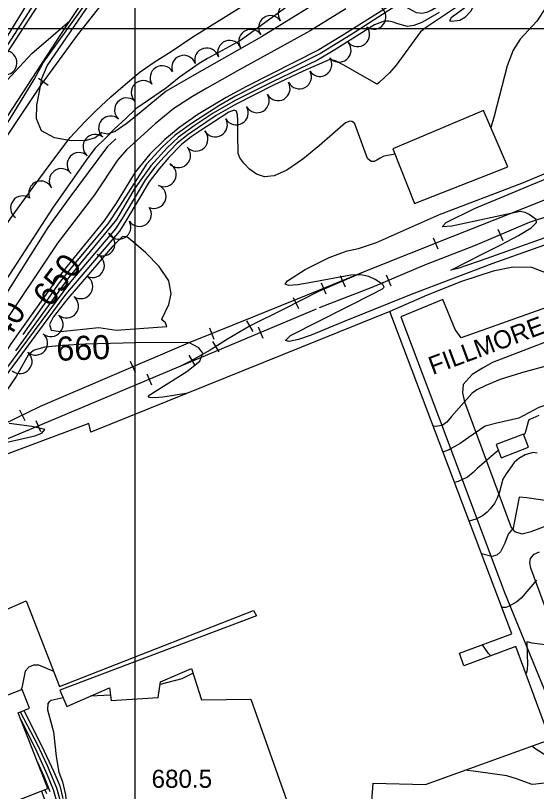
# Model space of a CAD drawing. Extents: x 79600 to 91800, y 75600 to 84400.
# Drawn here: x 83901 to 84333, y 81367 to 82011 of the extents above; entities that cross this region are included whole.
import ezdxf

# ---------------------------------------------------------------- set-up
doc = ezdxf.new("R2010")
doc.units = 0
for name, color, linetype in [('084-085$0$BLDG', 7, 'Continuous'), ('084-085$0$GRID', 7, 'Continuous'), ('084-085$0$INDEX', 7, 'Continuous'), ('084-085$0$INDXLBL', 7, 'Continuous'), ('084-085$0$INTER', 7, 'Continuous'), ('084-085$0$ROAD', 7, 'Continuous'), ('084-085$0$ROAD-NAME', 7, 'Continuous'), ('084-085$0$RR', 7, 'Continuous'), ('084-085$0$SPOTS', 7, 'Continuous'), ('084-085$0$TREES', 7, 'Continuous'), ('084-085$0$WALL', 7, 'Continuous')]:
    doc.layers.add(name, color=color, linetype=linetype)

# ---------------------------------------------------------------- blocks, each defined once
blk = doc.blocks.new('084-085$0$RRTICK100')
blk.add_line((0, -5), (0, 5))

msp = doc.modelspace()

# ---------------------------------------------------------------- linework, layer by layer
at = {"layer": '084-085$0$BLDG'}
for points in [[(84288.98, 81932.31), (84213.95, 81900.38), (84231.85, 81855.01), (84309.2, 81885.58)], [(84322.12, 81663.87), (84299.39, 81655.24), (84303.56, 81644.27), (84326.29, 81652.9)], [(83903.22, 81432.79), (83912.76, 81436.51), (83906.65, 81452.17), (83842.05, 81426.99), (83872.69, 81348.38), (83927.75, 81369.83)]]:
    msp.add_lwpolyline(points, close=True, dxfattribs=at)
for points in [[(84188.01, 81244.6), (84197.54, 81374.38), (84240.93, 81373.26), (84344.31, 81410.72), (84315.76, 81487.79), (84272.69, 81471.61), (84269.19, 81482.08), (84312.41, 81498.25), (84211.27, 81765.58), (84153.89, 81742.37)], [(84153.89, 81742.37), (83963.54, 81665.4), (83961.93, 81672.64), (83869.17, 81638.22), (83873.3, 81626.68), (83861.93, 81621.32), (83869.35, 81605.03), (83841.99, 81592.87), (83875.07, 81510.29), (83909.96, 81525.46), (83937.53, 81454.56), (84098.24, 81517.59), (84100.91, 81513.14), (83937.71, 81451.63), (83943.56, 81438.1), (83978.92, 81453.42), (83980.25, 81442.94), (84019.29, 81445.33), (84021.17, 81458.32), (84047, 81469.54), (84055.13, 81443.52), (84096.19, 81443.93), (84128.91, 81351.16)]]:
    msp.add_lwpolyline(points, dxfattribs=at)
at = {"layer": '084-085$0$GRID'}
for p, q in [((84000, 84000), (84000, 80000)), ((85000, 82000), (80000, 82000))]:
    msp.add_line(p, q, dxfattribs=at)
at = {"layer": '084-085$0$INDEX'}
msp.add_line((83979.7, 81447.28), (83963.14, 81446.59), dxfattribs=at)
for points in [[(84169.92, 82033.77), (84104.86, 81993.33), (84051.37, 81962.85), (84026.02, 81948.25), (84005.13, 81931.15), (83993.72, 81921.77), (83983.66, 81914.77), (83977.34, 81912.5), (83972.39, 81913.77), (83967.12, 81909.66), (83959.58, 81907.39), (83947.15, 81907), (83933.31, 81909.42), (83922.62, 81915.42), (83918.37, 81925.2), (83918.78, 81936.57), (83922.02, 81953.73), (83922.86, 81958.63), (83927.39, 81969.15), (83982.32, 82049.73)], [(84227.85, 82029.64), (84171.45, 81994.21), (84152.54, 81982.53), (84092.55, 81952.18), (84075.62, 81943.04), (84052.21, 81928.84), (84037.2, 81918.37), (84024.76, 81908.07), (84012.54, 81896.02), (84000.15, 81881.03), (83984.54, 81855.42), (83974.38, 81840.35), (83947.11, 81807.38), (83935.34, 81792.46), (83897.11, 81738.57), (83879.34, 81710.89), (83874.95, 81704.41), (83870.13, 81698.41), (83865, 81693.13), (83845.21, 81680.82), (83836.77, 81674.63), (83829.02, 81665.41), (83822.57, 81654.03), (83821.96, 81652.29)], [(84174.84, 82016.62), (84145.37, 81998.18), (84085.11, 81965.22), (84059.61, 81950.71), (84047.72, 81943.77), (84032.4, 81933.94), (84016.84, 81921.19), (83993.04, 81899.59), (83985.59, 81891), (83966.56, 81862.28), (83935.93, 81822.19), (83886.82, 81748.91), (83861.22, 81705.42), (83856.74, 81698.67), (83850.64, 81692.26), (83845.58, 81689.39), (83840.93, 81686.61), (83834.28, 81678.64), (83823.27, 81661.56), (83816.93, 81650.13)], [(83604.92, 81558.75), (83634.5, 81602.57), (83685.88, 81672.28), (83793.25, 81832.92), (83841.6, 81901.96), (83848.07, 81911.34), (83883.42, 81946.02), (83914.69, 81979.56), (83946.2, 82006.66)], [(84529.71, 81786.58), (84465.67, 81782.97), (84456.21, 81782.25), (84450.03, 81782.14), (84413.2, 81790.5), (84407.62, 81791.32), (84394.56, 81784.08), (84386.49, 81781.4), (84380.59, 81780.13), (84372.8, 81779.95), (84363.77, 81782.65), (84342.6, 81796.79), (84329.18, 81802.04), (84313.38, 81802.34), (84296.96, 81799.04), (84270.76, 81790.5), (84242.32, 81778.99), (84211.34, 81765.4)], [(84043.97, 81697.92), (84032.16, 81695.74), (84023.24, 81694.5), (84016.67, 81693.98), (84012.05, 81694.11), (84011.17, 81695.71), (84043.14, 81715.8), (84053.88, 81724.29), (84056.4, 81730.89), (84053.16, 81735.5), (84044.81, 81739.92), (84000.8, 81739.61), (83958.93, 81738.4), (83939.96, 81737.41), (83925.34, 81735.85), (83916.59, 81733.46), (83911.97, 81729.95), (83901.68, 81711.7), (83894.01, 81700.25)], [(84379.79, 81602.87), (84324.92, 81611.01), (84318.66, 81611.68), (84314.4, 81590.27), (84313.54, 81585.84), (84309.43, 81580.85), (84306.78, 81573.34), (84303.22, 81566.32), (84300.09, 81563.48), (84295.91, 81562.34), (84287.3, 81564.61)], [(84048.23, 81465.6), (84038.99, 81460.89), (84020.85, 81456.09)], [(83940.57, 81445.02), (83937.96, 81444.64), (83930.54, 81442.84), (83928.92, 81441.96), (83927.8, 81440.56), (83927.65, 81435.11), (83932.68, 81416.85), (83934.8, 81396.51), (83936.94, 81383.56), (83940.08, 81375.39), (83942.48, 81364.75), (83949.63, 81279.97), (83950.14, 81278.28), (83972.52, 81268.64)], [(83925.49, 81368.96), (83926.67, 81365.92)]]:
    msp.add_lwpolyline(points, dxfattribs=at)
msp.add_lwpolyline([(84023.3, 81757.95), (84022.36, 81759.27), (84028.2, 81771.21), (84030.2, 81780.09), (84028.11, 81790.9), (84020.17, 81802.85), (84009.23, 81814.18), (83999.28, 81822.87), (83993.22, 81827.34), (83989.73, 81827.8), (83981.32, 81819.2), (83958.2, 81792.46), (83944.42, 81776.32), (83932.17, 81760.75), (83929.2, 81754.62), (83930.59, 81750.1), (83938.46, 81748.8), (83970.24, 81752.27), (83984.56, 81750.16), (84022.89, 81752.86), (84026.59, 81753.2), (84025.32, 81756.24)], close=True, dxfattribs=at)
at = {"layer": '084-085$0$INTER'}
for points in [[(83827.07, 81893.84), (83866.25, 81948.15), (83909.82, 82018.91), (83968.43, 82107.74), (83991.66, 82148.08), (84004.18, 82166.83), (84040.06, 82229.4), (84055.65, 82258.83), (84067.32, 82282.61), (84076.02, 82301.62), (84088.64, 82337.49), (84098.62, 82367.46), (84107.62, 82399.91), (84111.25, 82414.7), (84112.87, 82431.55), (84113.11, 82441.23), (84112.46, 82451.06), (84110.51, 82459.35), (84107.66, 82465.08), (84104.48, 82467.43), (84101.46, 82465.93), (84096.44, 82456.38), (84076.61, 82406.02), (84072.37, 82396.44)], [(83830.23, 81893.53), (83868.81, 81946.74), (83973.86, 82109.38)], [(83832.44, 81893.32), (83842.73, 81907.78), (83871.37, 81945.33), (83979.37, 82111.1)], [(84411.51, 82105.38), (84407.28, 82106.88), (84398.38, 82106.5), (84388.07, 82103.33), (84377.99, 82098.79), (84365.61, 82092.27), (84363.9, 82091.34), (84360.31, 82074.3), (84353.28, 82046.9), (84347.5, 82031.78), (84340.64, 82017.71), (84333.34, 82006.27), (84319.5, 81991.27), (84313.55, 81982.29), (84308.51, 81969.2), (84297.71, 81927.42), (84295.25, 81918.81), (84295.07, 81918.23)], [(83924.01, 81971.65), (84013.77, 82096.81)], [(84337.43, 82079.59), (84289.66, 82043.53), (84266.36, 82027.17), (84251.47, 82018.39), (84246.28, 82015.47), (84241.89, 82013.47), (84237.77, 82012.71), (84233.52, 82013.31), (84221.44, 82019.7), (84217.64, 82019.81), (84181.22, 81996.39), (84153.98, 81979.41), (84102.14, 81953.63), (84083.51, 81943.99), (84069.48, 81936.13), (84046.85, 81921.53), (84033.53, 81911.69), (84022.73, 81901.8), (84009.69, 81887.65), (83986.66, 81851.93), (83977.61, 81838.27), (83949.34, 81804.41), (83937.15, 81789.23), (83907.02, 81746.44)], [(84275.74, 82024.12), (84249.14, 82006.25), (84242.53, 82001.82), (84236.77, 81997.34), (84216.71, 81969.87), (84210.99, 81963.34), (84202.61, 81955.54), (84200.76, 81954.04), (84172.65, 81970.15), (84166.21, 81973.29), (84161.66, 81974.42), (84139.61, 81964.84), (84115.06, 81953.13), (84082.98, 81936.92), (84067.53, 81927.93), (84044.24, 81912.29), (84035.11, 81905.11), (84024.24, 81893.88), (84016.66, 81885.18), (84008.89, 81875.04), (83990.91, 81844.94), (83984.05, 81834.11), (83946.72, 81790.07), (83892.82, 81717.35)], [(84252.22, 82013.5), (84237.8, 82005.29), (84231.21, 82002.6), (84225.94, 82001.9), (84217.91, 82004.1), (84214.18, 82005.42), (84210.41, 82006.23), (84206.58, 82006.21), (84198.7, 82003.24), (84165.68, 81982.56), (84151.4, 81974.05), (84113.96, 81956.04), (84083.24, 81940.45), (84065.05, 81929.91), (84049.26, 81919.46), (84036.31, 81910.11), (84026.65, 81901.2), (84013.18, 81886.41), (83999.41, 81866.94), (83984.69, 81841.72), (83944.88, 81793.43), (83901.09, 81732.89)], [(83769.13, 81629.53), (83768.81, 81632.01), (83767.11, 81644.67), (83766.71, 81655.72), (83767.91, 81665.31), (83779.39, 81690.76), (83781.32, 81699.6), (83777.62, 81720.29), (83777.92, 81733.13), (83783.14, 81747.87), (83791.34, 81762.66), (83880.19, 81898.79), (83916.58, 81957.79), (83924.01, 81971.65)], [(84215.74, 81895.86), (84206.52, 81894.22), (84203.45, 81892.73), (84200.5, 81890.91), (84198.36, 81889.79), (84195.8, 81889.77), (84192.96, 81892.36), (84183.55, 81917.99), (84181.99, 81921.78), (84179.99, 81922.98), (84178.08, 81923.47), (84174.48, 81921.95), (84153, 81903.12), (84139.28, 81891.93), (84126.05, 81882.69), (84115.53, 81877.93), (84107.44, 81877.25), (84100.82, 81879.5), (84095, 81883.57), (84090.21, 81888.4), (84086.95, 81892.95), (84085.5, 81896.5), (84085.41, 81912.8), (84085.39, 81923.91), (84085.2, 81928.53), (84084.28, 81931.53), (84082.35, 81932.41), (84077.83, 81930.87), (84054.08, 81915.32), (84046.58, 81910.26), (84038.56, 81904.12), (84028.14, 81893.16), (84020.15, 81883.94), (84011.8, 81873.05), (83993.03, 81841.44), (83987.27, 81832.03), (83942.6, 81779.55), (83891.53, 81710.56)], [(84449.6, 81866.95), (84359.94, 81833.86), (84291.87, 81809.54), (84267.7, 81801.29), (84261.82, 81799.76), (84287.88, 81813.02), (84303.47, 81820.84), (84317.93, 81828.58), (84328.38, 81835.01), (84332.82, 81839.25), (84332.63, 81841.89), (84326.93, 81845.87), (84323.41, 81847.6), (84319.26, 81848.53), (84262.84, 81836.35), (84254.61, 81835.8), (84257.93, 81839.26), (84281.43, 81850.91), (84451.03, 81921.3), (84475.78, 81931.96)], [(84390.03, 81838.44), (84296.01, 81804.98), (84229.06, 81779.75), (84172.26, 81756.59), (84146.07, 81745.94), (84135.66, 81742.42), (84127.87, 81740.72), (84124.85, 81741.51), (84129.12, 81745.49), (84198.93, 81781.11), (84202.53, 81782.88), (84205.18, 81784.37), (84206.68, 81785.6), (84205.65, 81787.78), (84199.27, 81792), (84194.02, 81794.49), (84187.31, 81795.99), (84179.07, 81795.77), (84146.18, 81789.53), (84135.1, 81787.72), (84127.29, 81787.14), (84124.53, 81788.3), (84126.49, 81791.07), (84141.05, 81800.31), (84161.06, 81810.32), (84176.02, 81815.81), (84185.34, 81817.66), (84200.36, 81822.75), (84252.42, 81845.91), (84320.82, 81871.83), (84421.71, 81913.88)], [(83984.3, 81908.6), (83983.45, 81907.85), (83977.43, 81902.45), (83945.39, 81859.09), (83927.75, 81835.06), (83879.36, 81758.34), (83846.03, 81698.88), (83840.98, 81693.46), (83821.47, 81662.96), (83812.33, 81648.15)], [(84530.51, 81784.66), (84467.23, 81765.84), (84428.77, 81747.65), (84416.36, 81739.8), (84407.34, 81730.49), (84396.4, 81726.29), (84391.05, 81724.47), (84387.06, 81723.67), (84384.24, 81723.82), (84377.38, 81728.67), (84375.27, 81729.58), (84320.42, 81714.61), (84302.86, 81708.99), (84290.98, 81704.26), (84283.36, 81700.44), (84279.27, 81697.62), (84262.4, 81678.5), (84258.48, 81673.71), (84254.87, 81671.03), (84248.83, 81670.25), (84247.13, 81670.79)], [(84531.22, 81782.57), (84454.43, 81753.34), (84436.47, 81746.39), (84431.03, 81743.6), (84427.82, 81741.07), (84426.25, 81738.72), (84425.2, 81716.14), (84425.02, 81711.26), (84424.37, 81708.3), (84401.62, 81693.75), (84389.64, 81682.93), (84378.7, 81689.86), (84374.01, 81691.83), (84368.4, 81692.71), (84355.55, 81691.3), (84344.74, 81689.3), (84334.96, 81685.91), (84318.4, 81677.09), (84300.19, 81672.94), (84290.43, 81670.45), (84276.23, 81660.64), (84269.79, 81655.92), (84259.72, 81650.51), (84255.4, 81648.93)], [(84334.94, 81679.15), (84327.54, 81675.86), (84326.17, 81675.13), (84324.22, 81666.96), (84323.26, 81664.14), (84322.41, 81663.12)], [(83894.18, 81657.19), (83917.17, 81662.48), (83922.79, 81664.59), (83925.27, 81667.74), (83914.68, 81670.18), (83895.87, 81672.77)], [(84301.29, 81650.25), (84283.64, 81635.36), (84280.43, 81631.95), (84275.7, 81628.22), (84267.99, 81624.64), (84264.9, 81623.81)], [(84333.39, 81647.98), (84330.2, 81648.62), (84323.41, 81646.77), (84318.2, 81643.68), (84314.43, 81640.43), (84307.83, 81631.03), (84304.96, 81626.43), (84302.15, 81616.05), (84300.28, 81610.85), (84297.99, 81606.42), (84294.62, 81601.96), (84291.93, 81599.1), (84288.06, 81596.08), (84282.53, 81593.32), (84277.03, 81591.77)], [(84332.96, 81542.64), (84320.2, 81527.9), (84316.69, 81524.72), (84310.26, 81521.04), (84307.45, 81520.07), (84304.77, 81519.99), (84303.89, 81520.77)], [(84295.2, 81480.06), (84293.23, 81482.05), (84288.05, 81489.13)], [(84354.84, 81487.04), (84329.47, 81490.44), (84326.22, 81491.25), (84324.94, 81491.48), (84325.2, 81480.26), (84325.45, 81473.84), (84325.32, 81468.37), (84324.5, 81465.22), (84324.18, 81465.06)], [(83932.72, 81466.93), (83920.34, 81472.14), (83915.98, 81472.28), (83912.02, 81470.56), (83909.08, 81467.25), (83906.33, 81453.57), (83905.56, 81451.74)], [(83904.86, 81433.43), (83918.95, 81406.6), (83927.24, 81389.07), (83935.08, 81370.62), (83938.35, 81358.62)], [(83908.06, 81434.68), (83923.01, 81405.06), (83932.93, 81383.79), (83937.88, 81372.19), (83940.41, 81361.69)], [(83905.42, 81427.13), (83918.71, 81400.27), (83927.38, 81381.39), (83932.28, 81369.06), (83936.28, 81355.56)], [(84339.92, 81397.93), (84332.33, 81402.68), (84329, 81405.17)], [(83918.53, 81393.51), (83919.38, 81391.76), (83924.6, 81380.19), (83929.47, 81367.49)], [(84348.42, 81375.42), (84332.5, 81373.61), (84329.36, 81373.28), (84316.27, 81378.03), (84308.32, 81380.53), (84282.58, 81383.99), (84273.61, 81385.1)], [(83922.62, 81367.84), (83927.23, 81354.72)]]:
    msp.add_lwpolyline(points, dxfattribs=at)
msp.add_lwpolyline([(84262.37, 82006.15), (84269.41, 82007.11), (84274.03, 82009.9), (84278.46, 82014.65), (84281.4, 82019.47), (84281.43, 82021.96), (84277.76, 82020.5), (84262.16, 82009), (84260.95, 82006.65)], close=True, dxfattribs=at)
at = {"layer": '084-085$0$ROAD'}
for points in [[(84047.99, 81993.38), (84127.32, 82042.8), (84141.83, 82052.22)], [(84129.09, 82020.43), (84087.44, 81990.32), (84060.17, 81975.37), (84053.36, 81971.13), (84036.64, 81959.52), (84026.28, 81950.91), (84011.42, 81940.71), (84000.73, 81933.49), (83992.54, 81925.66), (83982.8, 81916.74), (83976.16, 81909.85), (83967.2, 81900.94), (83961.03, 81892.97), (83932.22, 81851.9), (83878.48, 81769.46)], [(83853.8, 81777.98), (83896.83, 81842.65), (83915.63, 81868.58), (83935.21, 81895.29), (83946.47, 81909.67), (83958.36, 81922.65), (83967.94, 81932.19), (83979.99, 81943.46), (83992.21, 81954.11), (84004.27, 81964.14), (84016.81, 81972.92), (84029.97, 81981.09), (84047.99, 81993.38)], [(84512.33, 81833.38), (84362.15, 81776.33), (84270.62, 81743.78), (84265.45, 81750.67), (84255.17, 81775.43), (84220.58, 81761.19), (84257.36, 81663.67), (84306.52, 81532.47), (84367.27, 81383.93), (84370.13, 81375.93), (84371.88, 81370.23), (84373.69, 81359.29), (84361.37, 81184.25), (84359.08, 81180.98), (84353.69, 81179.7), (84350.75, 81180.28), (84175.56, 81185.76)], [(84390.26, 81385.24), (84328.24, 81552.6), (84327.42, 81557.22), (84328, 81560.78), (84330.9, 81564.36), (84335.51, 81566.26)]]:
    msp.add_lwpolyline(points, dxfattribs=at)
msp.add_lwpolyline([(84427.46, 81620.43), (84405.86, 81681.51), (84385.39, 81737.35), (84381.62, 81743.48), (84372.92, 81749.42), (84364.58, 81749.49), (84296.6, 81723.19), (84288.31, 81718.63), (84279.56, 81713.3), (84272.08, 81705.04), (84271.53, 81698.09), (84273.3, 81690.54), (84312, 81586.4), (84314.82, 81583.03), (84320.7, 81581.24), (84328.4, 81583.17), (84426.69, 81620.11)], close=True, dxfattribs=at)
at = {"layer": '084-085$0$RR'}
for points in [[(84082.89, 82149.04), (84061.1, 82124.17), (84042.26, 82104), (84026.51, 82086.33), (84008.3, 82065.38), (83989.01, 82041.62), (83968.81, 82015.69), (83952.3, 81994.75), (83922.4, 81953.67), (83895.75, 81914.01), (83840.91, 81833.28), (83775.76, 81737.1), (83712.45, 81642.95)], [(84481.96, 81915.3), (84322.05, 81850.81), (84262.69, 81827.38), (84191.95, 81799.2), (84152.31, 81783.06)], [(84486.41, 81903.29), (84362.34, 81850.9), (84326.95, 81839.28), (84282.21, 81820.31), (84240.23, 81803.84), (84196.41, 81785.5), (84152.87, 81768.46)], [(84191.95, 81799.2), (84153.52, 81782.6), (84152.35, 81782.02)], [(84152.31, 81783.06), (84099.84, 81761.7), (84044.17, 81739.38)], [(84152.35, 81782.02), (84123.41, 81767.49), (84095.6, 81753.62), (84076.72, 81742.48)], [(84150.27, 81767.44), (83821.99, 81629.49), (83795.79, 81618.13), (83751.44, 81599.35), (83717.01, 81584.98), (83672.67, 81565.42), (83634.99, 81550.1), (83595.13, 81534.15), (83557.45, 81518.05), (83523.03, 81503.53), (83488.13, 81489.63), (83442.81, 81470.26)], [(84044.17, 81739.38), (83921.6, 81686.87), (83890.91, 81671.9), (83861.45, 81659.59), (83838.49, 81650.58), (83818.18, 81642.21), (83798.95, 81634.63), (83769.48, 81622.32), (83733.67, 81606.23), (83697.71, 81589.52), (83661.12, 81572.19), (83624.85, 81554.7), (83587.34, 81536.43), (83537.42, 81513.42), (83502.09, 81495.93), (83479.91, 81486.62), (83430.14, 81464.7), (83341.75, 81428.07), (83206.83, 81373.26), (83150.85, 81349.9)], [(84076.72, 81742.48), (84062.32, 81733.47), (84046.21, 81724.35), (84037.25, 81719.9)]]:
    msp.add_lwpolyline(points, dxfattribs=at)
at = {"layer": '084-085$0$TREES'}
for centre, radius, start, end in [((84128.89, 82012.37), 10, 34.92575, 214.92575), ((84198.12, 82009.64), 10, 233.94065, 53.94065), ((84112.51, 82000.93), 9.98, 34.92575, 214.92575), ((84096.15, 81989.46), 10, 35.1222, 215.1222), ((84184.56, 81995.15), 10, 219.89146, 39.89146), ((84078.59, 81980.24), 10, 20.26975, 200.26975), ((84059.59, 81974.04), 10, 15.86896, 195.86896), ((84169.22, 81982.32), 10, 219.87827, 39.87827), ((83892.24, 81971.79), 10, 255.89375, 75.89375), ((84040.54, 81967.96), 10, 19.54003, 199.54003), ((84153.39, 81970.35), 9.87, 214.28752, 34.28752), ((84022.64, 81959.32), 10, 31.96463, 211.96463), ((84136.37, 81960.14), 10, 207.66453, 27.66453), ((84006.99, 81947.05), 10, 44.2462, 224.2462), ((84118.63, 81950.36), 10, 210.05064, 30.05064), ((84127.4, 81955.43), 0.135, 210.05064, 30.05064), ((84101.32, 81940.34), 10, 210.05064, 30.05064), ((83993.19, 81932.6), 10, 48.4135, 228.4135), ((84084, 81930.33), 10, 210.05064, 30.05064), ((83979.97, 81917.59), 10, 48.83891, 228.83891), ((84066.69, 81920.31), 10, 210.05064, 30.05064), ((84050.63, 81908.58), 10, 222.25468, 42.25468), ((83966.98, 81902.38), 10, 50.14442, 230.14442), ((84036.09, 81894.86), 10, 224.40292, 44.40292), ((83953.83, 81887.32), 10, 47.63993, 227.63993), ((84024.34, 81878.99), 10, 242.55958, 62.55958), ((83939.06, 81873.97), 10, 36.59473, 216.59473), ((83922.01, 81863.7), 10, 25.50558, 205.50558), ((84015.82, 81860.91), 10, 247.01109, 67.01109), ((83907.02, 81851.37), 10, 53.38049, 233.38049), ((84003.67, 81846.04), 10, 214.46569, 34.46569), ((83986.73, 81835.44), 10, 209.58839, 29.58839), ((83973.43, 81821.63), 10, 242.60262, 62.60262), ((83964.74, 81803.62), 10, 245.87137, 65.87137), ((83955.14, 81786.16), 10, 236.5206, 56.5206), ((83943.28, 81770.09), 10, 230.61616, 50.61616), ((83930.51, 81754.7), 10, 230.01211, 50.01211), ((83917.66, 81739.37), 10, 230.01211, 50.01211), ((83904.8, 81724.05), 10, 230.01211, 50.01211)]:
    msp.add_arc(centre, radius, start, end, dxfattribs=at)
at = {"layer": '084-085$0$WALL'}
msp.add_lwpolyline([(83656.62, 81581.04), (83673.69, 81603.13), (83730.72, 81684.21), (83802.53, 81790.57), (83862.48, 81878.67), (83939.19, 81996.11), (83986.18, 82066.86), (84036.53, 82147.9)], dxfattribs=at)

# ---------------------------------------------------------------- block references
at = {"layer": '084-085$0$RR'}
for p, rotation in [((83924.19, 81956.13), -126.05232809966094), ((84302.95, 81829.1), -157.02450576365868), ((84249.17, 81821.99), -158.27935270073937), ((84172.28, 81790.7), -156.65080361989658), ((84210.36, 81791.34), -157.286519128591), ((84156.38, 81784.71), -157.84703259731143), ((84133.49, 81772.55), -153.33760411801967), ((84063.68, 81747.2), -158.1526443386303), ((84095.17, 81753.37), -149.43958934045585), ((84104.17, 81748.07), -157.20637501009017), ((84067.04, 81736.42), -147.96100209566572), ((84047.3, 81724.96), -150.49119471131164), ((83998.21, 81719.69), -156.81062451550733), ((84011.98, 81709.33), -157.20637501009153), ((83906.63, 81679.57), -154.0068069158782), ((83919.79, 81670.59), -157.2063750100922)]:
    msp.add_blockref('084-085$0$RRTICK100', p, dxfattribs=dict(at, rotation=rotation))

# ---------------------------------------------------------------- texts
at = {"layer": '084-085$0$INDXLBL'}
for s, rotation, p in [('650', 52.58355, (83929.73, 81767.99)), ('640', 57.9844, (83886.94, 81727.88)), ('660', 2.1602, (83935.27, 81724.54))]:
    msp.add_text(s, height=20, rotation=rotation, dxfattribs=at).set_placement(p)
at = {"layer": '084-085$0$ROAD-NAME'}
msp.add_text('FILLMORE AVE.', height=15, rotation=20.49541, dxfattribs=at).set_placement((84246.89, 81712.82))
at = {"layer": '084-085$0$SPOTS'}
msp.add_text('680.5', height=15, dxfattribs=at).set_placement((84013.86, 81370.54))

doc.saveas('drawing.dxf')
